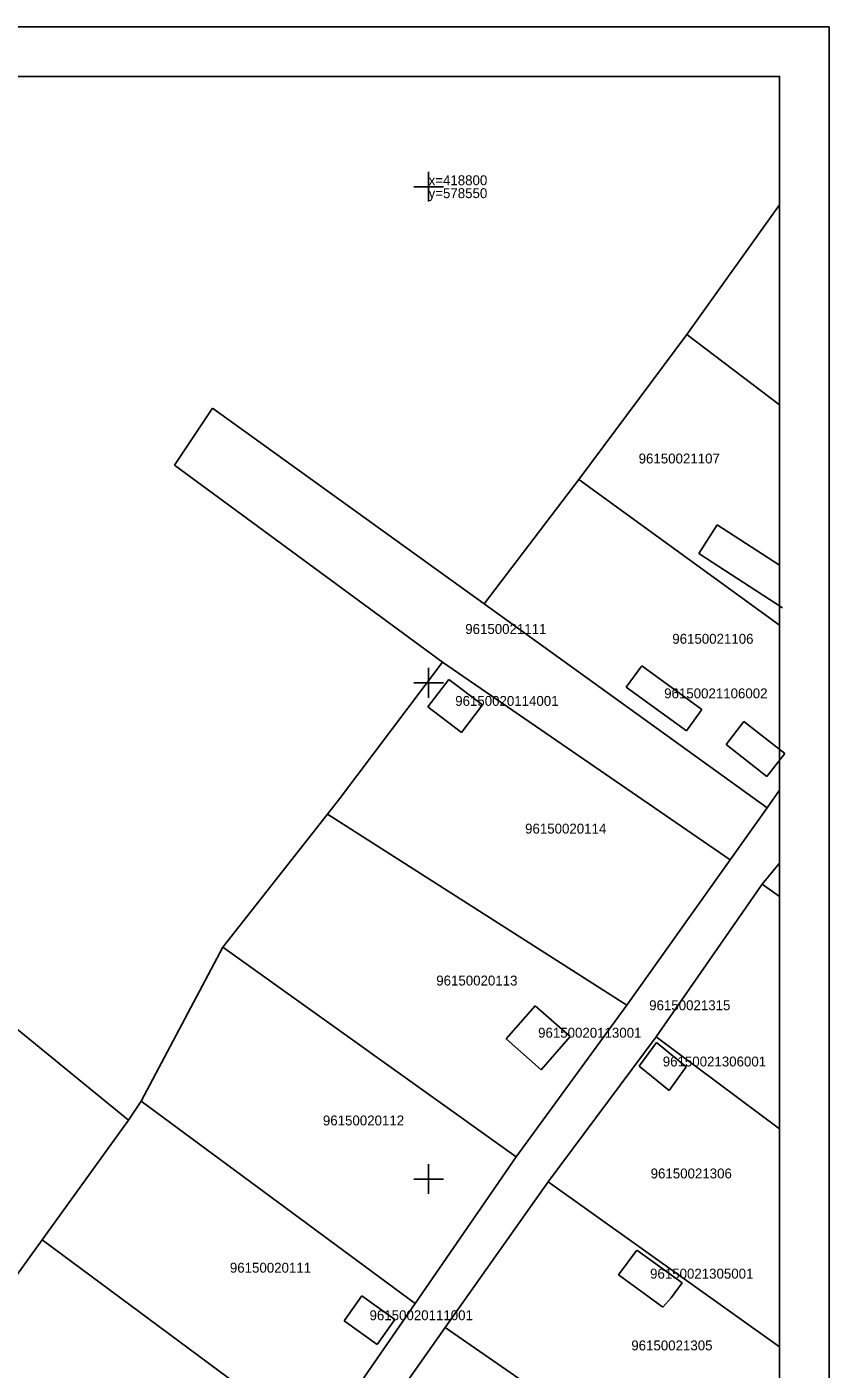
# Model space of a CAD drawing. Extents: x 578395 to 578590, y 418519 to 418816.
# Drawn here: x 578509.5 to 578590.4, y 418680.8 to 418816.1 of the extents above; entities that cross this region are included whole.
import ezdxf

# ---------------------------------------------------------------- set-up
doc = ezdxf.new("R2010")
doc.units = 0
for name, color, linetype in [('BUVE_EKAS_UZMR_####_#', 7, 'Continuous'), ('BUVE_EKAS_UZMR_TKST_#', 7, 'Continuous'), ('BUVE_EKAS_VEKT_####_#', 7, 'Continuous'), ('BUVE_EKAS_VEKT_TKST_#', 7, 'Continuous'), ('CELI_CMAL_####_####_#', 7, 'Continuous'), ('GEOD_ELEM_####_####_#', 7, 'Continuous'), ('GEOD_KORD_####_TKST_#', 7, 'Continuous'), ('RAMI_PLAN_####_TKST_#', 7, 'Continuous'), ('ROBZ_PROJ_####_####_#', 7, 'Continuous'), ('ROBZ_PROJ_####_TKST_#', 7, 'Continuous'), ('ROBZ_UZMR_####_####_#', 7, 'Continuous'), ('ROBZ_UZMR_####_TKST_#', 7, 'Continuous')]:
    doc.layers.add(name, color=color, linetype=linetype)

msp = doc.modelspace()

# ---------------------------------------------------------------- linework, layer by layer
at = {"layer": 'BUVE_EKAS_UZMR_####_#'}
for p, q in [((578577.21, 418763.03), (578579.06, 418765.93)), ((578579.06, 418765.93), (578585.35, 418761.86)), ((578585.66, 418757.56), (578577.21, 418763.03)), ((578571.22, 418711.37), (578572.96, 418713.76)), ((578572.96, 418713.76), (578575.96, 418711.31)), ((578574.23, 418708.92), (578571.22, 418711.37)), ((578575.96, 418711.31), (578574.23, 418708.92)), ((578569.12, 418690.35), (578570.97, 418692.83)), ((578570.97, 418692.83), (578575.54, 418689.52)), ((578571.72, 418688.47), (578569.12, 418690.35)), ((578575.54, 418689.52), (578574.42, 418688.02)), ((578541.48, 418685.71), (578543.28, 418688.23)), ((578543.28, 418688.23), (578546.61, 418685.83)), ((578573.61, 418687.08), (578571.72, 418688.47)), ((578574.42, 418688.02), (578573.61, 418687.08)), ((578544.81, 418683.31), (578541.48, 418685.71)), ((578546.61, 418685.83), (578544.81, 418683.31))]:
    msp.add_line(p, q, dxfattribs=at)
at = {"layer": 'BUVE_EKAS_VEKT_####_#'}
for p, q in [((578569.91, 418749.58), (578571.47, 418751.72)), ((578571.47, 418751.72), (578577.54, 418747.3)), ((578549.93, 418747.58), (578552.03, 418750.35)), ((578552.03, 418750.35), (578555.43, 418747.78)), ((578575.98, 418745.16), (578569.91, 418749.58)), ((578553.33, 418745.01), (578549.93, 418747.58)), ((578555.43, 418747.78), (578553.33, 418745.01)), ((578577.54, 418747.3), (578575.98, 418745.16)), ((578579.96, 418743.78), (578581.77, 418746.1)), ((578581.77, 418746.1), (578585.89, 418742.88)), ((578584.07, 418740.56), (578579.96, 418743.78)), ((578585.89, 418742.88), (578584.07, 418740.56)), ((578557.8, 418714.11), (578560.73, 418717.46)), ((578560.73, 418717.46), (578564.26, 418714.37)), ((578561.33, 418711.01), (578557.8, 418714.11)), ((578564.26, 418714.37), (578561.33, 418711.01))]:
    msp.add_line(p, q, dxfattribs=at)
at = {"layer": 'CELI_CMAL_####_####_#'}
msp.add_spline([(578540.02, 418586.37), (578525.99, 418597.85), (578512.59, 418608.64), (578501.67, 418618.24), (578486.37, 418629.74), (578473.85, 418639.53), (578461.4, 418649.85), (578445.48, 418664.31), (578434.89, 418671.62), (578433.59, 418673.24), (578433.71, 418674.57), (578434.34, 418682.51), (578433.83, 418698.67), (578431.51, 418715.15), (578429.96, 418730.38), (578428.63, 418741.31), (578426.86, 418755.17), (578424.46, 418771.37), (578422.35, 418787.38), (578420.6, 418802.68)], degree=3, dxfattribs=at)
at = {"layer": 'GEOD_ELEM_####_####_#'}
for p, q in [((578550, 418801.5), (578550, 418800)), ((578548.5, 418800), (578550, 418800)), ((578550, 418800), (578550, 418798.5)), ((578550, 418800), (578551.5, 418800)), ((578550, 418751.5), (578550, 418750)), ((578548.5, 418750), (578550, 418750)), ((578550, 418750), (578550, 418748.5)), ((578550, 418750), (578551.5, 418750)), ((578550, 418701.5), (578550, 418700)), ((578548.5, 418700), (578550, 418700)), ((578550, 418700), (578550, 418698.5)), ((578550, 418700), (578551.5, 418700))]:
    msp.add_line(p, q, dxfattribs=at)
at = {"layer": 'RAMI_PLAN_####_TKST_#'}
for p, q in [((578590.35, 418816.11), (578395.35, 418816.11)), ((578590.35, 418667.61), (578590.35, 418816.11))]:
    msp.add_line(p, q, dxfattribs=at)
msp.add_lwpolyline([(578410.35, 418811.11), (578410.35, 418524.11), (578585.35, 418524.11), (578585.35, 418811.11)], close=True, dxfattribs=at)
at = {"layer": 'ROBZ_PROJ_####_####_#'}
for p, q in [((578576, 418785.1), (578585.35, 418798.16)), ((578524.41, 418771.94), (578528.24, 418777.69)), ((578528.24, 418777.69), (578555.59, 418757.96)), ((578551.41, 418752.1), (578524.41, 418771.94)), ((578555.59, 418757.96), (578565.12, 418770.48)), ((578584.1, 418737.4), (578555.59, 418757.96)), ((578541.01, 418738.32), (578551.41, 418752.1)), ((578551.41, 418752.1), (578580.38, 418732.16)), ((578585.35, 418739.17), (578584.1, 418737.4)), ((578539.83, 418736.76), (578541.01, 418738.32)), ((578529.26, 418723.36), (578539.83, 418736.76)), ((578539.83, 418736.76), (578569.98, 418717.51)), ((578584.1, 418737.4), (578580.38, 418732.16)), ((578580.38, 418732.16), (578569.98, 418717.51)), ((578583.59, 418729.7), (578585.35, 418731.83)), ((578572.94, 418714.32), (578583.59, 418729.7)), ((578585.35, 418728.48), (578583.59, 418729.7)), ((578569.98, 418717.51), (578558.81, 418702.23)), ((578542.49, 418672.06), (578551.67, 418685.02))]:
    msp.add_line(p, q, dxfattribs=at)
at = {"layer": 'ROBZ_UZMR_####_####_#'}
for p, q in [((578565.12, 418770.48), (578576, 418785.1)), ((578576, 418785.1), (578585.35, 418778.03)), ((578585.35, 418755.81), (578565.12, 418770.48)), ((578490.52, 418729.76), (578519.75, 418705.92)), ((578521.03, 418707.84), (578529.26, 418723.36)), ((578529.26, 418723.36), (578558.81, 418702.23)), ((578562.04, 418699.7), (578572.94, 418714.32)), ((578572.94, 418714.32), (578585.35, 418705.05)), ((578519.75, 418705.92), (578521.03, 418707.84)), ((578521.03, 418707.84), (578548.65, 418687.44)), ((578511.07, 418693.87), (578519.75, 418705.92)), ((578558.81, 418702.23), (578548.65, 418687.44)), ((578551.67, 418685.02), (578562.04, 418699.7)), ((578562.04, 418699.7), (578585.35, 418683.1)), ((578500.28, 418678.93), (578511.07, 418693.87)), ((578511.07, 418693.87), (578538.85, 418673.28)), ((578548.65, 418687.44), (578538.85, 418673.28)), ((578579.6, 418665.77), (578551.67, 418685.02))]:
    msp.add_line(p, q, dxfattribs=at)

# ---------------------------------------------------------------- texts
at = {"layer": 'BUVE_EKAS_UZMR_TKST_#'}
for s, p in [('96150021306001', (578573.59, 418711.34)), ('96150021305001', (578572.31, 418689.96)), ('96150020111001', (578544.05, 418685.77))]:
    msp.add_text(s, height=1, dxfattribs=at).set_placement(p)
at = {"layer": 'BUVE_EKAS_VEKT_TKST_#'}
for s, p in [('96150020114001', (578552.68, 418747.68)), ('96150021106002', (578573.73, 418748.44)), ('96150020113001', (578561.03, 418714.24))]:
    msp.add_text(s, height=1, dxfattribs=at).set_placement(p)
at = {"layer": 'GEOD_KORD_####_TKST_#'}
for s, p in [('x=418800', (578550, 418800.15)), ('y=578550', (578550, 418798.85))]:
    msp.add_text(s, height=1, dxfattribs=at).set_placement(p)
at = {"layer": 'ROBZ_PROJ_####_TKST_#'}
for s, p in [('96150021111', (578553.69, 418754.93)), ('96150021106', (578574.55, 418753.94)), ('96150020114', (578559.72, 418734.81)), ('96150020113', (578550.77, 418719.5)), ('96150021315', (578572.22, 418717.01))]:
    msp.add_text(s, height=1, dxfattribs=at).set_placement(p)
at = {"layer": 'ROBZ_UZMR_####_TKST_#'}
for s, p in [('96150021107', (578571.16, 418772.11)), ('96150020112', (578539.35, 418705.4)), ('96150021306', (578572.37, 418700.06)), ('96150020111', (578529.98, 418690.56)), ('96150021305', (578570.42, 418682.73))]:
    msp.add_text(s, height=1, dxfattribs=at).set_placement(p)

doc.saveas('drawing.dxf')
